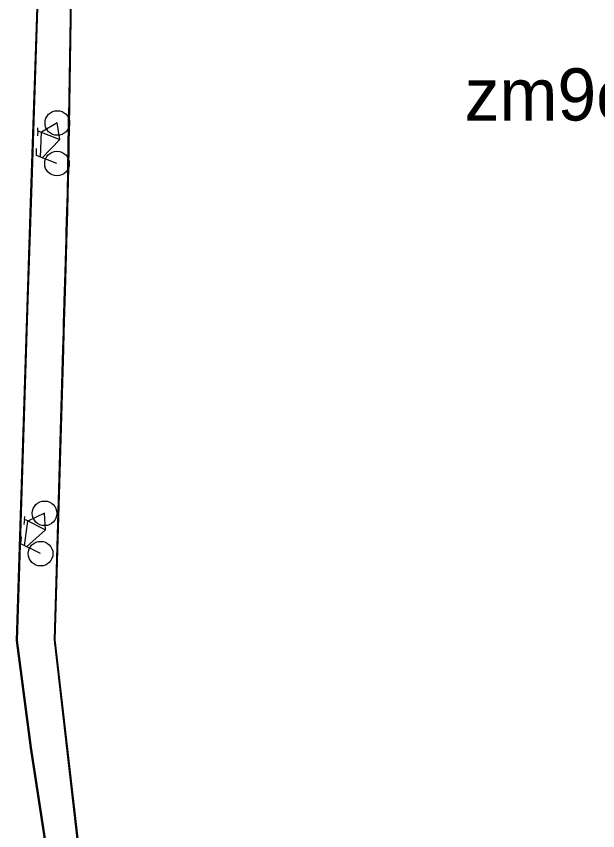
# Model space of a CAD drawing. Extents: x -555070 to -553076, y -1186731 to -1182766.
# Drawn here: x -554617.7 to -554416.9, y -1185038.3 to -1184757.3 of the extents above; entities that cross this region are included whole.
import ezdxf

# ---------------------------------------------------------------- set-up
doc = ezdxf.new("R2010")
doc.units = 0
for name, color, linetype in [('CYKLISTI_stav', 7, 'Continuous'), ('HRANICE_ZMENY_DO_KOO', 7, 'Continuous'), ('Level 10', 7, 'Continuous'), ('OBRYS_PLOCH', 7, 'Continuous'), ('stav_DS', 7, 'Continuous')]:
    doc.layers.add(name, color=color, linetype=linetype)

msp = doc.modelspace()

# ---------------------------------------------------------------- linework, layer by layer
at = {"layer": 'CYKLISTI_stav'}
for p, q in [((-554603.57, -1184794.08), (-554609.05, -1184797.25)), ((-554602.7, -1184799.76), (-554603.57, -1184794.08)), ((-554610.32, -1184796.74), (-554610.37, -1184798.56)), ((-554610.32, -1184796.74), (-554610.28, -1184795.75)), ((-554610.32, -1184796.74), (-554602.7, -1184799.76)), ((-554609.42, -1184805.9), (-554609.05, -1184797.25)), ((-554602.7, -1184799.76), (-554608.75, -1184806.15)), ((-554610.81, -1184805.36), (-554610.74, -1184802.92)), ((-554603.68, -1184808.08), (-554610.81, -1184805.36)), ((-554607.98, -1184928.79), (-554613.72, -1184931.46)), ((-554607.61, -1184934.53), (-554607.98, -1184928.79)), ((-554614.94, -1184930.84), (-554615.15, -1184932.65)), ((-554614.94, -1184930.84), (-554614.81, -1184929.86)), ((-554614.94, -1184930.84), (-554607.61, -1184934.53)), ((-554614.85, -1184940.04), (-554613.72, -1184931.46)), ((-554607.61, -1184934.53), (-554614.21, -1184940.35)), ((-554616.2, -1184939.38), (-554615.91, -1184936.95)), ((-554609.33, -1184942.72), (-554616.2, -1184939.38))]:
    msp.add_line(p, q, dxfattribs=at)
for centre in [(-554603.57, -1184794.09), (-554603.68, -1184808.08), (-554607.98, -1184928.8), (-554609.33, -1184942.72)]:
    msp.add_circle(centre, 4.25, dxfattribs=at)
at = {"layer": 'HRANICE_ZMENY_DO_KOO'}
for p, q in [((-554608.62, -1184692.09), (-554612.83, -1184818.2)), ((-554599.64, -1184809.83), (-554597.99, -1184712.84)), ((-554599.79, -1184818.41), (-554599.64, -1184809.83)), ((-554599.64, -1184809.83), (-554599.64, -1184809.83)), ((-554612.83, -1184818.2), (-554617.74, -1184972.72)), ((-554599.97, -1184824.63), (-554599.79, -1184818.41)), ((-554600.17, -1184831.5), (-554599.97, -1184824.63)), ((-554600.77, -1184852.17), (-554600.17, -1184831.5)), ((-554600.17, -1184831.5), (-554600.17, -1184831.5)), ((-554601.08, -1184862.78), (-554600.77, -1184852.17)), ((-554600.77, -1184852.17), (-554600.77, -1184852.17)), ((-554601.19, -1184866.43), (-554601.08, -1184862.78)), ((-554601.08, -1184862.78), (-554601.08, -1184862.78)), ((-554601.36, -1184872.18), (-554601.19, -1184866.43)), ((-554601.19, -1184866.43), (-554601.19, -1184866.43)), ((-554604.28, -1184972.41), (-554601.36, -1184872.2)), ((-554601.36, -1184872.2), (-554601.36, -1184872.18)), ((-554617.74, -1184972.72), (-554612.94, -1185009.71)), ((-554596.17, -1185043.07), (-554604.28, -1184972.41)), ((-554612.94, -1185009.71), (-554607.32, -1185045.94))]:
    msp.add_line(p, q, dxfattribs=at)
at = {"layer": 'OBRYS_PLOCH'}
for p, q in [((-554608.32, -1184692.11), (-554612.53, -1184818.21)), ((-554608.32, -1184692.11), (-554612.53, -1184818.21)), ((-554599.64, -1184792.05), (-554598.29, -1184712.84)), ((-554599.64, -1184792.05), (-554598.29, -1184712.84)), ((-554599.95, -1184810.13), (-554599.69, -1184794.64)), ((-554599.95, -1184810.13), (-554599.69, -1184794.64)), ((-554599.69, -1184794.64), (-554599.65, -1184792.36)), ((-554599.69, -1184794.64), (-554599.65, -1184792.36)), ((-554599.65, -1184792.36), (-554599.64, -1184792.05)), ((-554599.65, -1184792.36), (-554599.64, -1184792.05)), ((-554600.09, -1184818.4), (-554599.95, -1184810.13)), ((-554600.09, -1184818.4), (-554599.95, -1184810.13)), ((-554599.95, -1184810.13), (-554599.95, -1184810.13)), ((-554599.95, -1184810.13), (-554599.95, -1184810.13)), ((-554612.53, -1184818.21), (-554613.81, -1184858.51)), ((-554612.53, -1184818.21), (-554613.81, -1184858.51)), ((-554600.27, -1184824.62), (-554600.09, -1184818.4)), ((-554600.27, -1184824.62), (-554600.09, -1184818.4)), ((-554600.48, -1184831.8), (-554600.27, -1184824.62)), ((-554600.48, -1184831.8), (-554600.27, -1184824.62)), ((-554600.55, -1184834.32), (-554600.48, -1184831.8)), ((-554600.55, -1184834.32), (-554600.48, -1184831.8)), ((-554600.48, -1184831.8), (-554600.48, -1184831.8)), ((-554600.48, -1184831.8), (-554600.48, -1184831.8)), ((-554600.99, -1184849.27), (-554600.55, -1184834.32)), ((-554600.99, -1184849.27), (-554600.55, -1184834.32)), ((-554601.07, -1184851.86), (-554600.99, -1184849.27)), ((-554601.07, -1184851.86), (-554600.99, -1184849.27)), ((-554601.3, -1184859.91), (-554601.07, -1184851.86)), ((-554601.3, -1184859.91), (-554601.07, -1184851.86)), ((-554601.07, -1184851.86), (-554601.07, -1184851.86)), ((-554601.07, -1184851.86), (-554601.07, -1184851.86)), ((-554613.81, -1184858.51), (-554617.44, -1184972.71)), ((-554613.81, -1184858.51), (-554617.44, -1184972.71)), ((-554601.39, -1184863.08), (-554601.3, -1184859.91)), ((-554601.39, -1184863.08), (-554601.3, -1184859.91)), ((-554601.48, -1184866.13), (-554601.39, -1184863.08)), ((-554601.48, -1184866.13), (-554601.39, -1184863.08)), ((-554601.39, -1184863.08), (-554601.39, -1184863.08)), ((-554601.39, -1184863.08), (-554601.39, -1184863.08)), ((-554601.66, -1184872.17), (-554601.48, -1184866.13)), ((-554601.66, -1184872.17), (-554601.48, -1184866.13)), ((-554601.48, -1184866.13), (-554601.48, -1184866.13)), ((-554601.48, -1184866.13), (-554601.48, -1184866.13)), ((-554604.58, -1184972.42), (-554601.66, -1184872.19)), ((-554604.58, -1184972.42), (-554601.66, -1184872.19)), ((-554601.66, -1184872.19), (-554601.66, -1184872.17)), ((-554601.66, -1184872.19), (-554601.66, -1184872.17)), ((-554617.44, -1184972.71), (-554612.64, -1185009.67)), ((-554617.44, -1184972.71), (-554612.64, -1185009.67)), ((-554596.47, -1185043.12), (-554604.58, -1184972.42)), ((-554596.47, -1185043.12), (-554604.58, -1184972.42)), ((-554612.64, -1185009.67), (-554608.59, -1185035.81)), ((-554612.64, -1185009.67), (-554608.59, -1185035.81)), ((-554608.59, -1185035.81), (-554607.03, -1185045.88)), ((-554608.59, -1185035.81), (-554607.03, -1185045.88))]:
    msp.add_line(p, q, dxfattribs=at)
at = {"layer": 'stav_DS'}
for p, q in [((-554608.32, -1184692.11), (-554612.53, -1184818.21)), ((-554599.64, -1184792.05), (-554598.29, -1184712.84)), ((-554599.95, -1184810.13), (-554599.69, -1184794.64)), ((-554599.69, -1184794.64), (-554599.65, -1184792.36)), ((-554599.65, -1184792.36), (-554599.64, -1184792.05)), ((-554600.09, -1184818.4), (-554599.95, -1184810.13)), ((-554599.95, -1184810.13), (-554599.95, -1184810.13)), ((-554612.53, -1184818.21), (-554613.81, -1184858.51)), ((-554600.27, -1184824.62), (-554600.09, -1184818.4)), ((-554600.48, -1184831.8), (-554600.27, -1184824.62)), ((-554600.55, -1184834.32), (-554600.48, -1184831.8)), ((-554600.48, -1184831.8), (-554600.48, -1184831.8)), ((-554600.99, -1184849.27), (-554600.55, -1184834.32)), ((-554601.07, -1184851.86), (-554600.99, -1184849.27)), ((-554601.3, -1184859.91), (-554601.07, -1184851.86)), ((-554601.07, -1184851.86), (-554601.07, -1184851.86)), ((-554613.81, -1184858.51), (-554617.44, -1184972.71)), ((-554601.39, -1184863.08), (-554601.3, -1184859.91)), ((-554601.48, -1184866.13), (-554601.39, -1184863.08)), ((-554601.39, -1184863.08), (-554601.39, -1184863.08)), ((-554601.66, -1184872.17), (-554601.48, -1184866.13)), ((-554601.48, -1184866.13), (-554601.48, -1184866.13)), ((-554604.58, -1184972.42), (-554601.66, -1184872.19)), ((-554601.66, -1184872.19), (-554601.66, -1184872.17)), ((-554617.44, -1184972.71), (-554612.64, -1185009.67)), ((-554596.47, -1185043.12), (-554604.58, -1184972.42)), ((-554612.64, -1185009.67), (-554608.59, -1185035.81)), ((-554608.59, -1185035.81), (-554607.03, -1185045.88))]:
    msp.add_line(p, q, dxfattribs=at)

# ---------------------------------------------------------------- texts
at = {"layer": 'Level 10'}
msp.add_text('zm9e', height=18, dxfattribs=at).set_placement((-554462.93, -1184793.23))

doc.saveas('drawing.dxf')
